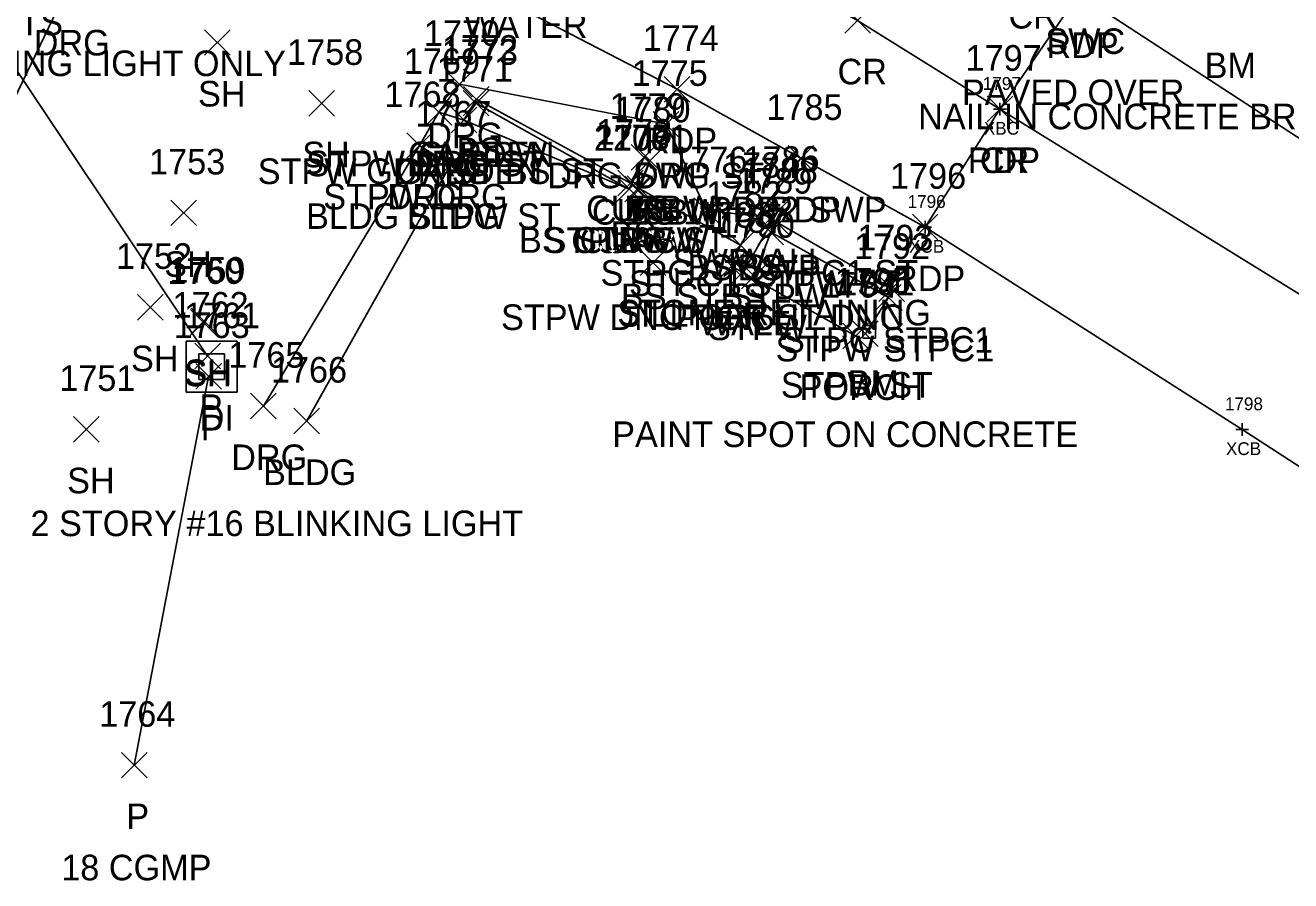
# Model space of a CAD drawing. Extents: x 1657482 to 1661439, y 647981 to 649041.
# Drawn here: x 1659908.5 to 1660007.4, y 647980.6 to 648047.4 of the extents above; entities that cross this region are included whole.
import ezdxf

# ---------------------------------------------------------------- set-up
doc = ezdxf.new("R2010")
doc.units = 0
for name, color, linetype in [('B_A', 7, 'Continuous'), ('B_I', 7, 'Continuous'), ('B_TIC', 7, 'Continuous'), ('BDC', 7, 'Continuous'), ('BELB', 7, 'Continuous'), ('C_A', 7, 'Continuous'), ('C_C', 7, 'Continuous'), ('C_I', 7, 'Continuous'), ('CPBM', 7, 'Continuous'), ('D_A', 7, 'Continuous'), ('D_C', 7, 'Continuous'), ('D_I', 7, 'Continuous'), ('D_TIC', 7, 'Continuous'), ('DCP', 7, 'Continuous'), ('DS', 7, 'Continuous'), ('L_A', 7, 'Continuous'), ('L_C', 7, 'Continuous'), ('L_I', 7, 'Continuous'), ('L_TIC', 7, 'Continuous'), ('LAPB', 7, 'Continuous'), ('LBC', 7, 'Continuous'), ('LBF', 7, 'Continuous'), ('LELB', 7, 'Continuous'), ('LW', 7, 'Continuous'), ('P_A', 7, 'Continuous'), ('P_I', 7, 'Continuous'), ('P_TIC', 7, 'Continuous'), ('PET', 7, 'Continuous'), ('PRC', 7, 'Continuous'), ('R_A', 7, 'Continuous'), ('R_C', 7, 'Continuous'), ('R_I', 7, 'Continuous'), ('R_TIC', 7, 'Continuous'), ('RC', 7, 'Continuous'), ('RDG', 7, 'Continuous'), ('RSW', 7, 'Continuous'), ('S_C', 7, 'Continuous'), ('U_C', 7, 'Continuous')]:
    doc.layers.add(name, color=color, linetype=linetype)

msp = doc.modelspace()

# ---------------------------------------------------------------- linework, layer by layer
at = {"layer": 'B_TIC'}
for p, q in [((1659984.714, 648040.852), (1659984.789, 648040.852)), ((1659978.869, 648031.627), (1659978.945, 648031.627)), ((1660003.635, 648015.816), (1660003.711, 648015.816))]:
    msp.add_line(p, q, dxfattribs=at)
for points in [[(1659984.21, 648040.852), (1659985.21, 648040.852)], [(1659984.71, 648040.352), (1659984.71, 648041.352)], [(1659978.866, 648031.127), (1659978.866, 648032.127)], [(1659978.366, 648031.627), (1659979.366, 648031.627)], [(1660003.632, 648015.316), (1660003.632, 648016.316)], [(1660003.132, 648015.816), (1660004.132, 648015.816)]]:
    msp.add_lwpolyline(points, dxfattribs=at)
at = {"layer": 'BDC'}
for points in [[(1660042.45, 648016.386), (1660019.758, 648030.97), (1659990.854, 648049.845)], [(1659978.866, 648031.627), (1660003.632, 648015.816), (1660030.713, 647998.276)]]:
    msp.add_lwpolyline(points, dxfattribs=at)
at = {"layer": 'BELB'}
msp.add_lwpolyline([(1659984.71, 648040.852), (1660010.636, 648024.833), (1660036.744, 648007.069)], dxfattribs=at)
at = {"layer": 'CPBM'}
for p, q in [((1659973.983, 648022.943), (1659973.983, 648023.943)), ((1659973.983, 648023.943), (1659974.983, 648023.943)), ((1659974.486, 648023.444), (1659974.486, 648023.444)), ((1659974.486, 648023.444), (1659974.486, 648023.444)), ((1659974.983, 648023.943), (1659974.983, 648022.943)), ((1659974.983, 648022.943), (1659973.983, 648022.943))]:
    msp.add_line(p, q, dxfattribs=at)
at = {"layer": 'D_TIC'}
for points in [[(1659921.789, 648020.554), (1659923.789, 648022.554)], [(1659923.789, 648020.554), (1659921.789, 648022.554)], [(1659921.874, 648018.96), (1659923.874, 648020.96)], [(1659923.874, 648018.96), (1659921.874, 648020.96)], [(1659916.062, 647988.58), (1659918.062, 647990.58)], [(1659918.062, 647988.58), (1659916.062, 647990.58)]]:
    msp.add_lwpolyline(points, dxfattribs=at)
at = {"layer": 'DCP'}
for points in [[(1659891.836, 648067.894), (1659922.789, 648021.554)], [(1659922.874, 648019.96), (1659917.062, 647989.58)]]:
    msp.add_lwpolyline(points, dxfattribs=at)
at = {"layer": 'DS'}
for p, q in [((1659921.113, 648022.724), (1659925.113, 648022.724)), ((1659921.113, 648018.724), (1659921.113, 648022.724)), ((1659925.113, 648022.724), (1659925.113, 648018.724)), ((1659922.113, 648019.724), (1659922.113, 648021.724)), ((1659922.113, 648021.724), (1659924.113, 648021.724)), ((1659924.113, 648021.724), (1659924.113, 648019.724)), ((1659923.118, 648020.725), (1659923.118, 648020.725)), ((1659923.118, 648020.725), (1659923.118, 648020.725)), ((1659924.113, 648019.724), (1659922.113, 648019.724)), ((1659925.113, 648018.724), (1659921.113, 648018.724))]:
    msp.add_line(p, q, dxfattribs=at)
at = {"layer": 'L_TIC'}
for points in [[(1659922.556, 648045.053), (1659924.556, 648047.053)], [(1659924.556, 648045.053), (1659922.556, 648047.053)], [(1659930.699, 648040.305), (1659932.699, 648042.305)], [(1659932.699, 648040.305), (1659930.699, 648042.305)], [(1659942.774, 648040.315), (1659944.774, 648042.315)], [(1659944.774, 648040.315), (1659942.774, 648042.315)], [(1659942.797, 648040.629), (1659944.797, 648042.629)], [(1659944.797, 648040.629), (1659942.797, 648042.629)], [(1659939.872, 648039.601), (1659941.872, 648041.601)], [(1659941.872, 648039.601), (1659939.872, 648041.601)], [(1659941.827, 648038.995), (1659943.827, 648040.995)], [(1659943.827, 648038.995), (1659941.827, 648040.995)], [(1659941.827, 648038.995), (1659943.827, 648040.995)], [(1659943.827, 648038.995), (1659941.827, 648040.995)], [(1659941.827, 648038.995), (1659943.827, 648040.995)], [(1659943.827, 648038.995), (1659941.827, 648040.995)], [(1659938.348, 648037.006), (1659940.348, 648039.006)], [(1659940.348, 648037.006), (1659938.348, 648039.006)], [(1659955.903, 648036.089), (1659957.903, 648038.089)], [(1659957.903, 648036.089), (1659955.903, 648038.089)], [(1659940.767, 648035.49), (1659942.767, 648037.49)], [(1659942.767, 648035.49), (1659940.767, 648037.49)], [(1659940.767, 648035.49), (1659942.767, 648037.49)], [(1659942.767, 648035.49), (1659940.767, 648037.49)], [(1659956.361, 648035.818), (1659958.361, 648037.818)], [(1659958.361, 648035.818), (1659956.361, 648037.818)], [(1659954.838, 648034.073), (1659956.838, 648036.073)], [(1659956.838, 648034.073), (1659954.838, 648036.073)], [(1659954.744, 648033.601), (1659956.744, 648035.601)], [(1659956.744, 648033.601), (1659954.744, 648035.601)], [(1659955.565, 648033.625), (1659957.565, 648035.625)], [(1659957.565, 648033.625), (1659955.565, 648035.625)], [(1659955.565, 648033.625), (1659957.565, 648035.625)], [(1659957.565, 648033.625), (1659955.565, 648035.625)], [(1659966.41, 648031.945), (1659968.41, 648033.945)], [(1659968.41, 648031.945), (1659966.41, 648033.945)], [(1659919.914, 648031.741), (1659921.914, 648033.741)], [(1659921.914, 648031.741), (1659919.914, 648033.741)], [(1659964.766, 648031.476), (1659966.766, 648033.476)], [(1659966.766, 648031.476), (1659964.766, 648033.476)], [(1659966.218, 648031.052), (1659968.218, 648033.052)], [(1659968.218, 648031.052), (1659966.218, 648033.052)], [(1659966.218, 648031.052), (1659968.218, 648033.052)], [(1659968.218, 648031.052), (1659966.218, 648033.052)], [(1659965.799, 648030.245), (1659967.799, 648032.245)], [(1659967.799, 648030.245), (1659965.799, 648032.245)], [(1659965.799, 648030.245), (1659967.799, 648032.245)], [(1659967.799, 648030.245), (1659965.799, 648032.245)], [(1659963.435, 648029.216), (1659965.435, 648031.216)], [(1659965.435, 648029.216), (1659963.435, 648031.216)], [(1659963.435, 648029.216), (1659965.435, 648031.216)], [(1659965.435, 648029.216), (1659963.435, 648031.216)], [(1659956.604, 648027.842), (1659958.604, 648029.842)], [(1659958.604, 648027.842), (1659956.604, 648029.842)], [(1659962.731, 648027.587), (1659964.731, 648029.587)], [(1659964.731, 648027.587), (1659962.731, 648029.587)], [(1659962.731, 648027.587), (1659964.731, 648029.587)], [(1659964.731, 648027.587), (1659962.731, 648029.587)], [(1659963.685, 648027.179), (1659965.685, 648029.179)], [(1659965.685, 648027.179), (1659963.685, 648029.179)], [(1659964.511, 648026.797), (1659966.511, 648028.797)], [(1659966.511, 648026.797), (1659964.511, 648028.797)], [(1659974.995, 648025.134), (1659976.995, 648027.134)], [(1659976.995, 648025.134), (1659974.995, 648027.134)], [(1659974.995, 648025.134), (1659976.995, 648027.134)], [(1659976.995, 648025.134), (1659974.995, 648027.134)], [(1659975.248, 648025.808), (1659977.248, 648027.808)], [(1659977.248, 648025.808), (1659975.248, 648027.808)], [(1659975.248, 648025.808), (1659977.248, 648027.808)], [(1659977.248, 648025.808), (1659975.248, 648027.808)], [(1659917.318, 648024.362), (1659919.318, 648026.362)], [(1659919.318, 648024.362), (1659917.318, 648026.362)], [(1659921.466, 648023.19), (1659923.466, 648025.19)], [(1659923.466, 648023.19), (1659921.466, 648025.19)], [(1659921.504, 648023.285), (1659923.504, 648025.285)], [(1659923.504, 648023.285), (1659921.504, 648025.285)], [(1659972.429, 648022.122), (1659974.429, 648024.122)], [(1659974.429, 648022.122), (1659972.429, 648024.122)], [(1659973.192, 648022.295), (1659975.192, 648024.295)], [(1659975.192, 648022.295), (1659973.192, 648024.295)], [(1659929.534, 648015.477), (1659931.534, 648017.477)], [(1659931.534, 648015.477), (1659929.534, 648017.477)], [(1659912.325, 648014.825), (1659914.325, 648016.825)], [(1659914.325, 648014.825), (1659912.325, 648016.825)]]:
    msp.add_lwpolyline(points, dxfattribs=at)
at = {"layer": 'LAPB'}
msp.add_lwpolyline([(1659942.827, 648039.995), (1659943.774, 648041.315)], dxfattribs=at)
at = {"layer": 'LBC'}
msp.add_lwpolyline([(1659930.534, 648016.477), (1659941.767, 648036.49)], dxfattribs=at)
at = {"layer": 'LBF'}
for points in [[(1659941.767, 648036.49), (1659939.348, 648038.006), (1659940.872, 648040.601), (1659942.827, 648039.995), (1659955.744, 648034.601)], [(1659956.565, 648034.625), (1659964.435, 648030.216), (1659963.731, 648028.587)], [(1659967.218, 648032.052), (1659966.799, 648031.245), (1659975.995, 648026.134), (1659976.248, 648026.808)], [(1659967.218, 648032.052), (1659976.248, 648026.808)], [(1659966.799, 648031.245), (1659965.511, 648027.797)], [(1659963.731, 648028.587), (1659973.429, 648023.122)], [(1659974.192, 648023.295), (1659975.995, 648026.134)]]:
    msp.add_lwpolyline(points, dxfattribs=at)
at = {"layer": 'LELB'}
for points in [[(1659942.827, 648039.995), (1659943.797, 648041.629), (1659955.838, 648035.073), (1659956.903, 648037.089), (1659957.361, 648036.818), (1659956.565, 648034.625)], [(1659964.435, 648030.216), (1659965.766, 648032.476)]]:
    msp.add_lwpolyline(points, dxfattribs=at)
at = {"layer": 'LW'}
msp.add_lwpolyline([(1659967.41, 648032.945), (1659964.685, 648028.179)], dxfattribs=at)
at = {"layer": 'P_TIC'}
for points in [[(1659972.585, 648046.782), (1659974.585, 648048.782)], [(1659974.585, 648046.782), (1659972.585, 648048.782)], [(1659958.475, 648041.397), (1659960.475, 648043.397)], [(1659960.475, 648041.397), (1659958.475, 648043.397)], [(1659983.71, 648039.852), (1659985.71, 648041.852)], [(1659985.71, 648039.852), (1659983.71, 648041.852)], [(1659983.71, 648039.852), (1659985.71, 648041.852)], [(1659985.71, 648039.852), (1659983.71, 648041.852)], [(1659968.15, 648036.003), (1659970.15, 648038.003)], [(1659970.15, 648036.003), (1659968.15, 648038.003)], [(1659977.866, 648030.627), (1659979.866, 648032.627)], [(1659979.866, 648030.627), (1659977.866, 648032.627)]]:
    msp.add_lwpolyline(points, dxfattribs=at)
at = {"layer": 'PET'}
msp.add_lwpolyline([(1659863.28, 648081.701), (1659868.598, 648080.447), (1659876.948, 648078.161), (1659883.344, 648076.024), (1659889.16, 648073.962), (1659894.185, 648071.763), (1659897.898, 648070.646), (1659905.34, 648067.906), (1659912.798, 648065.014), (1659924.735, 648059.408), (1659938.824, 648053.114), (1659959.475, 648042.397), (1659969.15, 648037.003), (1659978.866, 648031.627), (1659984.71, 648040.852), (1659990.854, 648049.845), (1659987.428, 648053.134), (1659983.709, 648058.695), (1659981.789, 648065.569), (1659981.786, 648070.317), (1659983.864, 648077.674), (1659998.695, 648097.495), (1660020.131, 648123.934)], dxfattribs=at)
at = {"layer": 'PRC'}
msp.add_lwpolyline([(1659891.684, 648086.345), (1659903.341, 648081.608), (1659918.7, 648074.839), (1659936.602, 648066.916), (1659955.342, 648057.99), (1659973.585, 648047.782), (1659984.71, 648040.852)], dxfattribs=at)
at = {"layer": 'R_TIC'}
for points in [[(1659941.469, 648041.794), (1659943.469, 648043.794)], [(1659943.469, 648041.794), (1659941.469, 648043.794)], [(1659942.774, 648040.315), (1659944.774, 648042.315)], [(1659944.774, 648040.315), (1659942.774, 648042.315)], [(1659939.872, 648039.601), (1659941.872, 648041.601)], [(1659941.872, 648039.601), (1659939.872, 648041.601)], [(1659957.618, 648038.665), (1659959.618, 648040.665)], [(1659959.618, 648038.665), (1659957.618, 648040.665)], [(1659957.618, 648038.665), (1659959.618, 648040.665)], [(1659959.618, 648038.665), (1659957.618, 648040.665)], [(1659938.348, 648037.006), (1659940.348, 648039.006)], [(1659940.348, 648037.006), (1659938.348, 648039.006)], [(1659955.903, 648036.089), (1659957.903, 648038.089)], [(1659957.903, 648036.089), (1659955.903, 648038.089)], [(1659968.15, 648036.003), (1659970.15, 648038.003)], [(1659970.15, 648036.003), (1659968.15, 648038.003)], [(1659956.361, 648035.818), (1659958.361, 648037.818)], [(1659958.361, 648035.818), (1659956.361, 648037.818)], [(1659954.744, 648033.601), (1659956.744, 648035.601)], [(1659956.744, 648033.601), (1659954.744, 648035.601)], [(1659955.4, 648033.6), (1659957.4, 648035.6)], [(1659957.4, 648033.6), (1659955.4, 648035.6)], [(1659960.776, 648031.918), (1659962.776, 648033.918)], [(1659962.776, 648031.918), (1659960.776, 648033.918)], [(1659964.766, 648031.476), (1659966.766, 648033.476)], [(1659966.766, 648031.476), (1659964.766, 648033.476)], [(1659926.148, 648016.641), (1659928.148, 648018.641)], [(1659928.148, 648016.641), (1659926.148, 648018.641)]]:
    msp.add_lwpolyline(points, dxfattribs=at)
at = {"layer": 'RC'}
for points in [[(1659943.774, 648041.315), (1659955.744, 648034.601), (1659956.903, 648037.089)], [(1659957.361, 648036.818), (1659956.4, 648034.6)]]:
    msp.add_lwpolyline(points, dxfattribs=at)
at = {"layer": 'RDG'}
for points in [[(1659913.188, 648060.644), (1659911.716, 648050.041), (1659897.454, 648020.47)], [(1659940.872, 648040.601), (1659942.469, 648042.794), (1659958.618, 648039.665)], [(1659927.148, 648017.641), (1659939.348, 648038.006)]]:
    msp.add_lwpolyline(points, dxfattribs=at)
at = {"layer": 'RSW'}
msp.add_lwpolyline([(1659958.618, 648039.665), (1659961.776, 648032.918), (1659965.766, 648032.476), (1659969.15, 648037.003)], dxfattribs=at)

# ---------------------------------------------------------------- texts
at = {"layer": 'B_A'}
for s, p in [('XBC', (1659983.446, 648038.852)), ('XCB', (1659977.602, 648029.627)), ('XCB', (1660002.368, 648013.816))]:
    msp.add_text(s, height=1, dxfattribs=at).set_placement(p)
at = {"layer": 'B_I'}
for s, p in [('1797', (1659983.364, 648042.352)), ('1796', (1659977.492, 648033.127)), ('1798', (1660002.285, 648017.316))]:
    msp.add_text(s, height=1, dxfattribs=at).set_placement(p)
at = {"layer": 'C_A'}
for p in [(1660000.702, 648043.273), (1659972.801, 648018.444)]:
    msp.add_text('BM', height=2, dxfattribs=at).set_placement(p)
at = {"layer": 'C_C'}
for s, p in [('NAIL IN CONCRETE BRIDGE CURB', (1659978.317, 648039.273)), ('PAINT SPOT ON CONCRETE', (1659954.407, 648014.444))]:
    msp.add_text(s, height=2, dxfattribs=at).set_placement(p)
at = {"layer": 'C_I'}
msp.add_text('1795', height=2, dxfattribs=at).set_placement((1659971.793, 648026.444))
at = {"layer": 'D_A'}
for s, p in [('P', (1659922.167, 648016.554)), ('DI', (1659922.173, 648015.725)), ('P', (1659922.252, 648014.96)), ('P', (1659916.44, 647984.58))]:
    msp.add_text(s, height=2, dxfattribs=at).set_placement(p)
at = {"layer": 'D_C'}
msp.add_text('18 CGMP', height=2, dxfattribs=at).set_placement((1659911.353, 647980.58))
at = {"layer": 'D_I'}
for s, p in [('1762', (1659920.049, 648024.554)), ('1761', (1659920.945, 648023.725)), ('1763', (1659920.134, 648022.96)), ('1764', (1659914.322, 647992.58))]:
    msp.add_text(s, height=2, dxfattribs=at).set_placement(p)
at = {"layer": 'L_A'}
for s, p in [('TS', (1659908.07, 648046.621)), ('SH', (1659922.044, 648041.053)), ('SH', (1659930.187, 648036.305)), ('GARDEN', (1659938.444, 648036.315)), ('BS', (1659942.238, 648036.629)), ('STPW GDN ST BS ST', (1659926.709, 648034.995)), ('STPW DRG ST', (1659930.486, 648035.601)), ('GARDEN', (1659937.496, 648034.995)), ('BS', (1659941.268, 648034.995)), ('STPW DRG', (1659931.829, 648033.006)), ('BS', (1659955.344, 648032.089)), ('BLDG STPW ST', (1659930.484, 648031.49)), ('BLDG', (1659938.358, 648031.49)), ('BS', (1659955.802, 648031.818)), ('BS', (1659954.279, 648030.073)), ('BS STPW ST', (1659947.124, 648029.625)), ('STPW CW', (1659949.051, 648029.601)), ('BS', (1659955.006, 648029.625)), ('SH', (1659919.403, 648027.741)), ('STPC ST STPC1 ST', (1659953.494, 648027.052)), ('STPC ST STPC1 ST', (1659953.494, 648027.052)), ('WALL', (1659963.898, 648027.945)), ('BS', (1659964.207, 648027.476)), ('STPC1 STPW ST', (1659955.721, 648026.245)), ('STPC1 STPW ST', (1659955.721, 648026.245)), ('BS ST STPW', (1659955.096, 648025.216)), ('BS', (1659962.876, 648025.216)), ('STPW DNC POR ST DNC', (1659945.723, 648023.587)), ('SILL', (1659954.864, 648023.842)), ('PORCH', (1659959.353, 648023.587)), ('WALL', (1659961.173, 648023.179)), ('STPW', (1659961.904, 648022.797)), ('STPW STPC1', (1659967.177, 648021.134)), ('STPW STPC1', (1659967.177, 648021.134)), ('STPC STPC1', (1659967.681, 648021.808)), ('STPC STPC1', (1659967.681, 648021.808)), ('SH', (1659916.806, 648020.362)), ('SH', (1659920.954, 648019.19)), ('SH', (1659920.993, 648019.285)), ('STPW ST', (1659967.586, 648018.295)), ('PORCH', (1659969.051, 648018.122)), ('BLDG', (1659927.124, 648011.477)), ('SH', (1659911.813, 648010.825))]:
    msp.add_text(s, height=2, dxfattribs=at).set_placement(p)
at = {"layer": 'L_C'}
for s, p in [('STONE RETAINING', (1659954.804, 648023.945)), ('2 STORY #16 BLINKING LIGHT', (1659908.952, 648007.477))]:
    msp.add_text(s, height=2, dxfattribs=at).set_placement(p)
at = {"layer": 'L_I'}
for s, p in [('1758', (1659929.006, 648044.305)), ('1773', (1659941.082, 648044.315)), ('1772', (1659941.104, 648044.629)), ('1769', (1659938.124, 648043.601)), ('1771', (1659940.701, 648042.995)), ('1771', (1659940.701, 648042.995)), ('1771', (1659940.701, 648042.995)), ('1768', (1659936.608, 648041.006)), ('1779', (1659954.203, 648040.089)), ('1780', (1659954.581, 648039.818)), ('1767', (1659939.027, 648039.49)), ('1767', (1659939.027, 648039.49)), ('1778', (1659953.145, 648038.073)), ('1777', (1659953.051, 648037.601)), ('1781', (1659954.439, 648037.625)), ('1781', (1659954.439, 648037.625)), ('1786', (1659964.662, 648035.945)), ('1753', (1659918.222, 648035.741)), ('1784', (1659963.074, 648035.476)), ('1788', (1659964.526, 648035.052)), ('1788', (1659964.526, 648035.052)), ('1789', (1659964.099, 648034.245)), ('1789', (1659964.099, 648034.245)), ('1782', (1659961.742, 648033.216)), ('1782', (1659961.742, 648033.216)), ('1541', (1659955.478, 648031.842)), ('1783', (1659961.038, 648031.587)), ('1783', (1659961.038, 648031.587)), ('1787', (1659961.992, 648031.179)), ('1790', (1659962.731, 648030.797)), ('1792', (1659973.303, 648029.134)), ('1792', (1659973.303, 648029.134)), ('1793', (1659973.555, 648029.808)), ('1793', (1659973.555, 648029.808)), ('1752', (1659915.625, 648028.362)), ('1760', (1659919.64, 648027.19)), ('1759', (1659919.804, 648027.285)), ('1794', (1659970.736, 648026.122)), ('1791', (1659972.067, 648026.295)), ('1766', (1659927.739, 648019.477)), ('1751', (1659911.199, 648018.825))]:
    msp.add_text(s, height=2, dxfattribs=at).set_placement(p)
at = {"layer": 'P_A'}
for s, p in [('CR', (1659985.373, 648047.146)), ('RDP', (1659988.342, 648044.845)), ('CR', (1659972.018, 648042.782)), ('RDP', (1659956.963, 648037.397)), ('CR', (1659983.143, 648035.852)), ('RDP', (1659982.198, 648035.852)), ('RDP', (1659966.639, 648032.003)), ('RDP', (1659976.354, 648026.627))]:
    msp.add_text(s, height=2, dxfattribs=at).set_placement(p)
at = {"layer": 'P_I'}
for s, p in [('1774', (1659956.782, 648045.397)), ('1797', (1659982.017, 648043.852)), ('1797', (1659982.017, 648043.852)), ('1785', (1659966.458, 648040.003)), ('1796', (1659976.118, 648034.627))]:
    msp.add_text(s, height=2, dxfattribs=at).set_placement(p)
at = {"layer": 'R_A'}
for s, p in [('DRG', (1659909.204, 648045.041)), ('SWC', (1659988.257, 648045.159)), ('DRG', (1659939.958, 648037.794)), ('CURBW', (1659939.239, 648036.315)), ('DRG', (1659938.36, 648035.601)), ('DRG SWP ST', (1659949.334, 648034.665)), ('DRG', (1659956.106, 648034.665)), ('DRG', (1659936.837, 648033.006)), ('CURBW', (1659952.368, 648032.089)), ('RDP2 SWP', (1659961.883, 648032.003)), ('CURBW', (1659952.825, 648031.818)), ('CURBW', (1659951.208, 648029.601)), ('CURBW', (1659951.865, 648029.6)), ('SWP', (1659959.138, 648027.918)), ('BS SWP', (1659960.294, 648027.476)), ('DRG', (1659924.636, 648012.641))]:
    msp.add_text(s, height=2, dxfattribs=at).set_placement(p)
at = {"layer": 'R_C'}
msp.add_text('PAVED OVER', height=2, dxfattribs=at).set_placement((1659981.738, 648041.159))
at = {"layer": 'R_I'}
for s, p in [('1770', (1659939.69, 648045.794)), ('1773', (1659941.082, 648044.315)), ('1769', (1659938.124, 648043.601)), ('1775', (1659955.925, 648042.665)), ('1775', (1659955.925, 648042.665)), ('1768', (1659936.608, 648041.006)), ('1779', (1659954.203, 648040.089)), ('1780', (1659954.581, 648039.818)), ('1785', (1659966.458, 648040.003)), ('2200', (1659952.975, 648037.6)), ('1777', (1659953.051, 648037.601)), ('1776', (1659959.028, 648035.918)), ('1784', (1659963.074, 648035.476)), ('1765', (1659924.408, 648020.641))]:
    msp.add_text(s, height=2, dxfattribs=at).set_placement(p)
at = {"layer": 'S_C'}
msp.add_text('PARKING FOR BLINKING LIGHT ONLY', height=2, dxfattribs=at).set_placement((1659880.628, 648043.429))
at = {"layer": 'U_C'}
msp.add_text('WATER', height=2, dxfattribs=at).set_placement((1659942.82, 648046.419))

doc.saveas('drawing.dxf')
